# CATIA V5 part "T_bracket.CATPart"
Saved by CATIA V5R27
Part number: T_bracket
Revision: ANY
Definition: UNKNOWN
Nomenclature: T_bracket
Source: Unknown
Bounding box of the stored display mesh (mm): x 0 to 114.3, y 0 to 114.3, z -3.175 to 3.175
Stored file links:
  \\triton.meca.polymtl.ca\usagers\zaoue\profiles\Desktop\varm_ass\bearing assy\T_bracket.CATPart
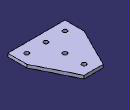
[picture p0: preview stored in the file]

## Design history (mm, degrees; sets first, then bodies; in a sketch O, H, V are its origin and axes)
Body1 "Boss-Extrude1" (main body)
  Solid1: solid without history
